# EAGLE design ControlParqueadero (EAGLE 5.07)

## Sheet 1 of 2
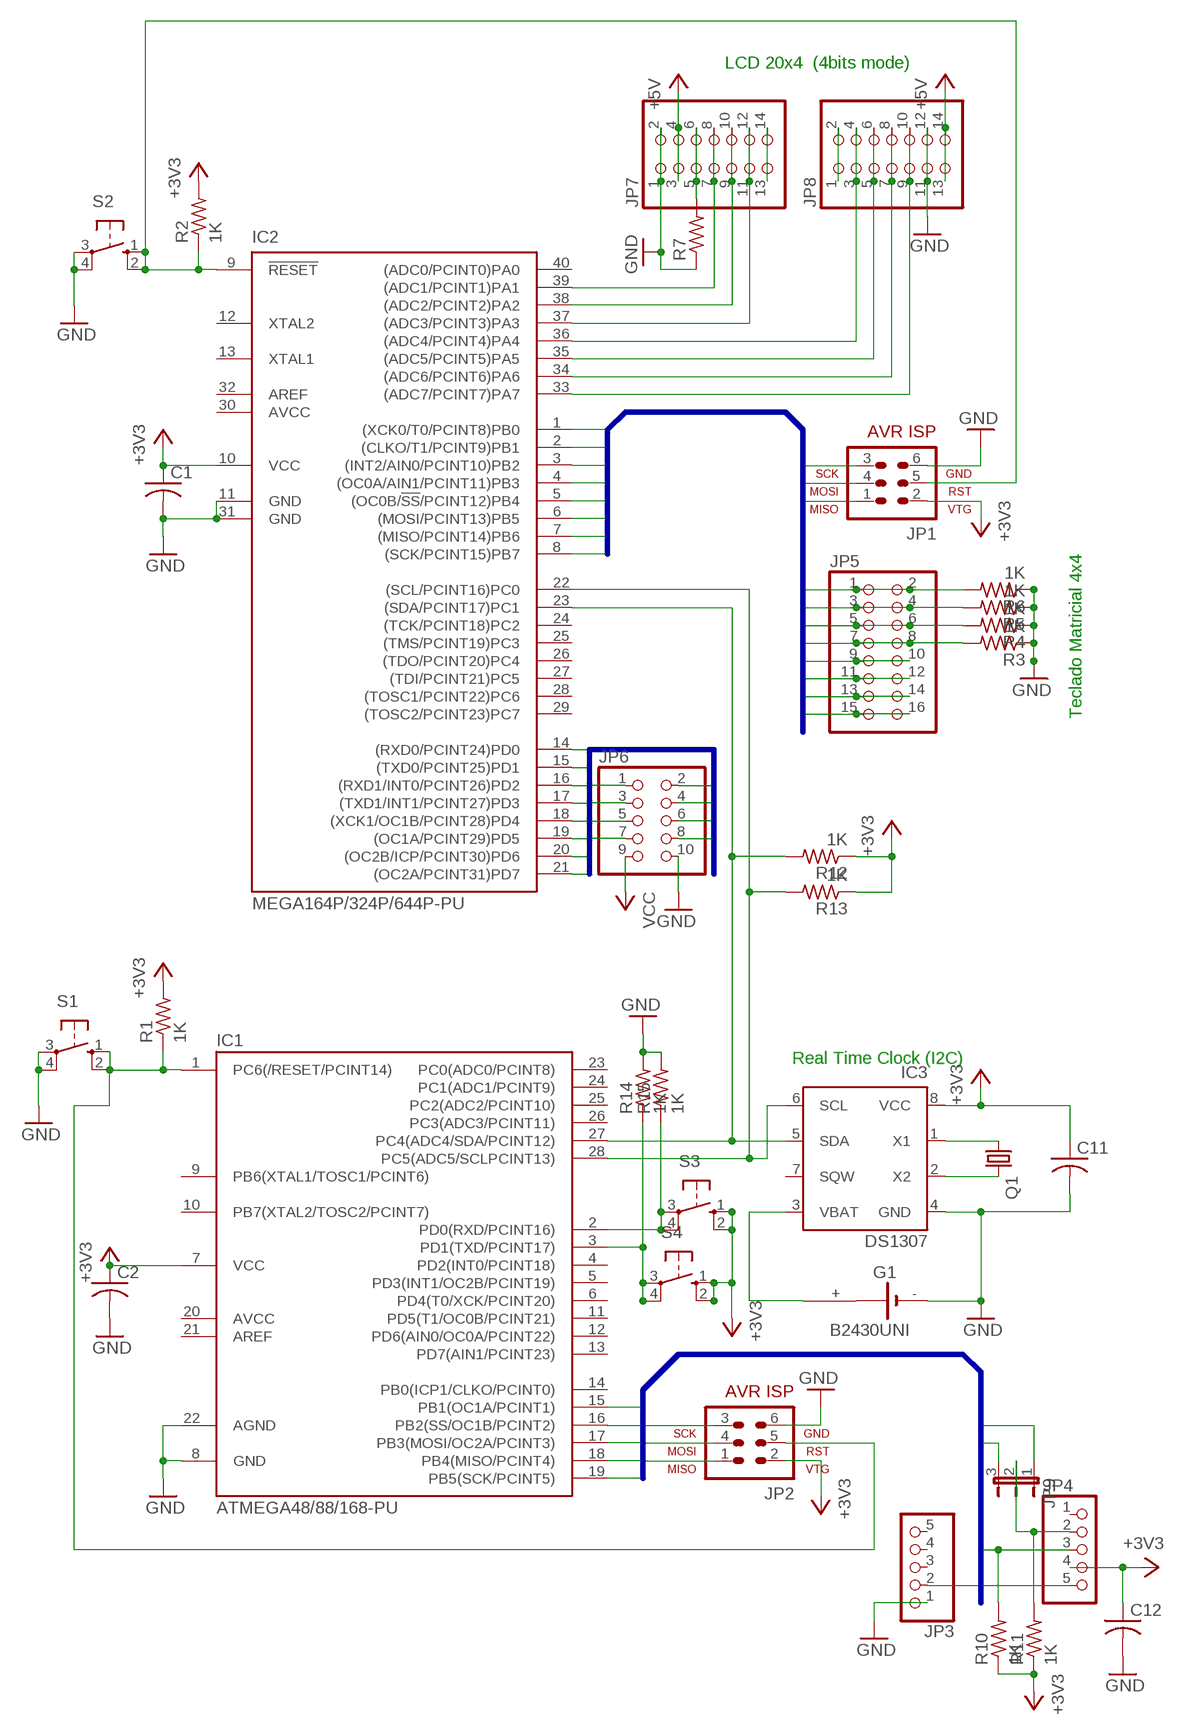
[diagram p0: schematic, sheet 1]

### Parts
C1  C-US025-025X050  [C025-025X050]
C2  C-US025-025X050  [C025-025X050]
C11  C-US025-025X050  [C025-025X050]
C12  C-US025-025X050  [C025-025X050]
G1  B2430UNI  [B2430UNI]
IC1  ATMEGA48/88/168-PU  [DIL28-3]
IC2  MEGA164P/324P/644P-PU  [DIL40]
IC3  DS1307  [DIL08]
JP1  AVR-ISP-6  [AVR-ISP-6]
JP2  AVR-ISP-6  [AVR-ISP-6]
JP3  PINHD-1X5  [1X05]
JP4  PINHD-1X5  [1X05]
JP5  PINHD-2X8  [2X08]
JP6  PINHD-2X5  [2X05]
JP7  PINHD-2X7  [2X07]
JP8  PINHD-2X7  [2X07]
JP9  JP2E  [JP2]
Q1  CRYSTALTC26V  [TC26V]
R1  1K  R-US_0204/7  [0204/7]
R2  1K  R-US_0204/7  [0204/7]
R3  1K  R-US_0204/7  [0204/7]
R4  1K  R-US_0204/7  [0204/7]
R5  1K  R-US_0204/7  [0204/7]
R6  1K  R-US_0204/7  [0204/7]
R7  R-US_0204/7  [0204/7]
R10  1K  R-US_0204/7  [0204/7]
R11  1K  R-US_0204/7  [0204/7]
R12  1K  R-US_0204/7  [0204/7]
R13  1K  R-US_0204/7  [0204/7]
R14  1K  R-US_0204/7  [0204/7]
R15  1K  R-US_0204/7  [0204/7]
S1  10-XX  [B3F-10XX]
S2  10-XX  [B3F-10XX]
S3  10-XX  [B3F-10XX]
S4  10-XX  [B3F-10XX]

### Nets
+3V3: C1.1 C2.1 C11.1 C12.1 IC1.7(VCC) IC2.10(VCC) IC3.8(VCC) JP1.2 JP2.2 JP4.4 R1.2 R2.2 R10.1 R11.1 R12.1 R13.1 S3.1(S) S3.2(S1) S4.1(S) S4.2(S1) ; also sheet 2
+5V: JP7.3 JP7.4 JP8.13 JP8.14 ; also sheet 2
GND: C1.2 C2.2 C11.2 C12.2 G1.- IC1.8(GND) IC1.22(AGND) IC2.11(GND) IC2.31(GND) IC3.4(GND) JP1.6 JP2.6 JP3.1 JP6.10 JP7.1 JP7.2 JP8.11 JP8.12 R3.1 R4.1 R5.1 R6.1 R7.1 R14.2 R15.2 S1.3(P) S1.4(P1) S2.3(P) S2.4(P1) ; also sheet 2
N$1: IC1.1(PC6(/RESET/PCINT14)) JP2.5 R1.1 S1.1(S) S1.2(S1)
N$2: IC1.2(PD0(RXD/PCINT16)) R15.1 S3.3(P) S3.4(P1)
N$3: IC2.9(!RESET) JP1.5 R2.1 S2.1(S) S2.2(S1)
N$4: IC1.3(PD1(TXD/PCINT17)) R14.1 S4.3(P) S4.4(P1)
N$5: JP4.2 JP9.2 R11.2
N$9: IC1.27(PC4(ADC4/SDA/PCINT12)) IC2.23((SDA/PCINT17)PC1) IC3.5(SDA) R12.2
N$11: IC1.28(PC5(ADC5/SCLPCINT13)) IC2.22((SCL/PCINT16)PC0) IC3.6(SCL) R13.2
N$19: IC3.2(X2) Q1.2
N$22: G1.+ IC3.3(VBAT)
N$27: IC2.33((ADC7/PCINT7)PA7) JP8.9 JP8.10
N$28: IC2.34((ADC6/PCINT6)PA6) JP8.7 JP8.8
N$29: IC2.35((ADC5/PCINT5)PA5) JP8.5 JP8.6
N$30: IC2.36((ADC4/PCINT4)PA4) JP8.3 JP8.4
N$32: IC3.1(X1) Q1.1
N$37: JP7.5 JP7.6 R7.2
N$38: IC2.39((ADC1/PCINT1)PA1) JP7.7 JP7.8
N$39: IC2.38((ADC2/PCINT2)PA2) JP7.9 JP7.10
N$40: IC2.37((ADC3/PCINT3)PA3) JP7.11 JP7.12
N$41: JP7.13 JP7.14
N$42: JP8.1 JP8.2
PORTB1: IC1.15(PB1(OC1A/PCINT1)) JP9.1
PORTB2: IC1.16(PB2(SS/OC1B/PCINT2)) JP9.3
PORTB3: IC1.17(PB3(MOSI/OC2A/PCINT3)) JP2.4 JP4.3 R10.2
PORTB4: IC1.18(PB4(MISO/PCINT4)) JP2.1 JP3.2
PORTB5: IC1.19(PB5(SCK/PCINT5)) JP2.3 JP4.5
PORTB_A0: IC2.1((XCK0/T0/PCINT8)PB0) JP5.1 JP5.2 R6.2
PORTB_A1: IC2.2((CLKO/T1/PCINT9)PB1) JP5.3 JP5.4 R5.2
PORTB_A2: IC2.3((INT2/AIN0/PCINT10)PB2) JP5.5 JP5.6 R4.2
PORTB_A3: IC2.4((OC0A/AIN1/PCINT11)PB3) JP5.7 JP5.8 R3.2
PORTB_A4: IC2.5((OC0B/!SS!/PCINT12)PB4) JP5.9 JP5.10
PORTB_A5: IC2.6((MOSI/PCINT13)PB5) JP1.4 JP5.11 JP5.12
PORTB_A6: IC2.7((MISO/PCINT14)PB6) JP1.1 JP5.13 JP5.14
PORTB_A7: IC2.8((SCK/PCINT15)PB7) JP1.3 JP5.15 JP5.16
PORTC0: IC2.14((RXD0/PCINT24)PD0) JP6.1
PORTC1: IC2.15((TXD0/PCINT25)PD1) JP6.2
PORTC2: IC2.16((RXD1/INT0/PCINT26)PD2) JP6.3
PORTC3: IC2.17((TXD1/INT1/PCINT27)PD3) JP6.4
PORTC4: IC2.18((XCK1/OC1B/PCINT28)PD4) JP6.5
PORTC5: IC2.19((OC1A/PCINT29)PD5) JP6.6
PORTC6: IC2.20((OC2B/ICP/PCINT30)PD6) JP6.7
PORTC7: IC2.21((OC2A/PCINT31)PD7) JP6.8
VCC: JP6.9 ; also sheet 2
Unconnected: G1.+@1(+) G1.+@2(+) G1.+@3(+) G1.+@4(+) G1.-@1(-) IC1.4(PD2(INT0/PCINT18)) IC1.5(PD3(INT1/OC2B/PCINT19)) IC1.6(PD4(T0/XCK/PCINT20)) IC1.9(PB6(XTAL1/TOSC1/PCINT6)) IC1.10(PB7(XTAL2/TOSC2/PCINT7)) IC1.11(PD5(T1/OC0B/PCINT21)) IC1.12(PD6(AIN0/OC0A/PCINT22)) IC1.13(PD7(AIN1/PCINT23)) IC1.14(PB0(ICP1/CLKO/PCINT0)) IC1.20(AVCC) IC1.21(AREF) IC1.23(PC0(ADC0/PCINT8)) IC1.24(PC1(ADC1/PCINT9)) IC1.25(PC2(ADC2/PCINT10)) IC1.26(PC3(ADC3/PCINT11)) IC2.12(XTAL2) IC2.13(XTAL1) IC2.24((TCK/PCINT18)PC2) IC2.25((TMS/PCINT19)PC3) IC2.26((TDO/PCINT20)PC4) IC2.27((TDI/PCINT21)PC5) IC2.28((TOSC1/PCINT22)PC6) IC2.29((TOSC2/PCINT23)PC7) IC2.40((ADC0/PCINT0)PA0) IC3.7(SQW) JP3.3 JP3.4 JP3.5 JP4.1

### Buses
PORTB[0..5]
PORTC[0..7]
PORTB_A[0..7]

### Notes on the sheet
- LCD 20x4  (4bits mode)
- Teclado Matricial 4x4
- Real Time Clock (I2C)

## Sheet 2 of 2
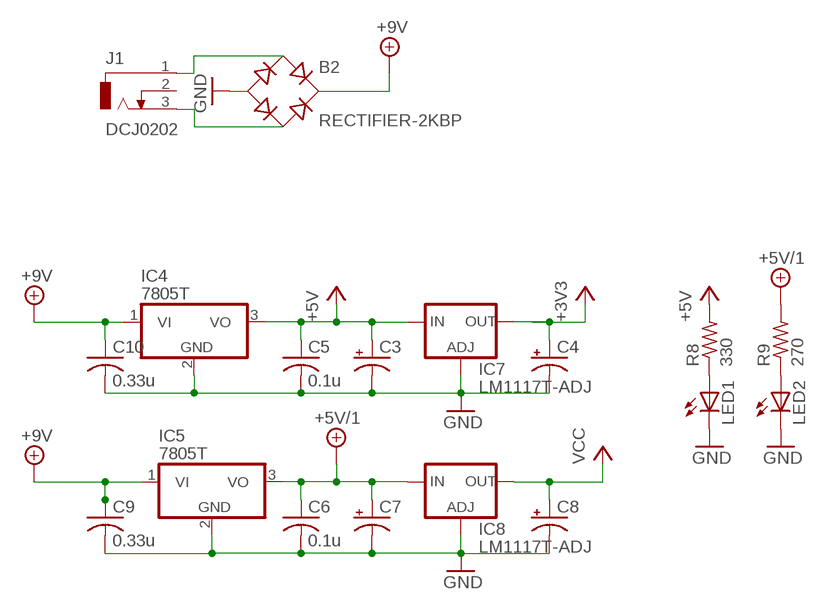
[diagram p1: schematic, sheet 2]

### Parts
B2  RECTIFIER-2KBP  [2KBP]
C3  CPOL-USE5-8.5  [E5-8,5]
C4  CPOL-USE5-8.5  [E5-8,5]
C5  0.1u  C-US025-025X050  [C025-025X050]
C6  0.1u  C-US025-025X050  [C025-025X050]
C7  CPOL-USE5-8.5  [E5-8,5]
C8  CPOL-USE5-8.5  [E5-8,5]
C9  0.33u  C-US050-035X075  [C050-035X075]
C10  0.33u  C-US050-035X075  [C050-035X075]
IC4  7805T  [TO220H]
IC5  7805T  [TO220H]
IC7  LM1117T-ADJ  [TO220]
IC8  LM1117T-ADJ  [TO220]
J1  DCJ0202  [DCJ0202]
LED1  LED5MM  [LED5MM]
LED2  LED5MM  [LED5MM]
R8  330  R-US_0204/7  [0204/7]
R9  270  R-US_0204/7  [0204/7]

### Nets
+3V3: C4.+ IC7.2(OUT) ; also sheet 1
+5V: C3.+ C5.1 IC4.3(VO) IC7.3(IN) R8.2 ; also sheet 1
+5V/1: C6.1 C7.+ IC5.3(VO) IC8.3(IN) R9.2
+9V: B2.+ C9.1 C10.1 IC4.1(VI) IC5.1(VI)
GND: B2.- C3.- C4.- C5.2 C6.2 C7.- C8.- C9.2 C10.2 IC4.2(GND) IC5.2(GND) IC7.1(ADJ) IC8.1(ADJ) LED1.K(C) LED2.K(C) ; also sheet 1
N$21: LED1.A R8.1
N$23: B2.AC1 J1.1
N$24: B2.AC2 J1.3
N$25: LED2.A R9.1
VCC: C8.+ IC8.2(OUT) ; also sheet 1
Unconnected: J1.2

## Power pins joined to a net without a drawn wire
AREF: IC2.32(AREF)
AVCC: IC2.30(AVCC)

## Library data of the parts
B2 = rectifier:RECTIFIER-: Rectifier
C1 C2 C5 C6 C9-C12 = rcl:C-US: CAPACITOR, American symbol
C3 C4 C7 C8 = rcl:CPOL-US: POLARIZED CAPACITOR, American symbol
G1 = battery:B2430UNI: LI BATTERY
IC1 = atmega8:ATMEGA48/88/168-PU
IC2 = avr-6:MEGA164P/324P/644P-PU
IC3 = ds1307_pcf8583:DS1307: I2C-Bus CLOCK/CALENDAR
IC4 IC5 = linear:78*: Positive VOLTAGE REGULATOR Source: http://cache.national.com/ds/LM/LM78L05.pdf http://www.fairchildsemi.com/ds/LM/LM7805.pdf
IC7 IC8 = lm1117:LM1117T-ADJ
J1 = con-jack:DCJ0202: DC POWER JACK Source: DCJ0202.pdf
JP1 JP2 = avr-6:AVR-ISP-6: AVR ISP-6 Serial Programming Header
JP3 JP4 = pinhead:PINHD-1X5: PIN HEADER
JP5 = pinhead:PINHD-2X8: PIN HEADER
JP6 = pinhead:PINHD-2X5: PIN HEADER
JP7 JP8 = pinhead:PINHD-2X7: PIN HEADER
JP9 = jumper:JP2E: JUMPER
LED1 LED2 = led:LED: LED
Q1 = crystal:CRYSTAL: CRYSTAL
R1-R15 = rcl:R-US_: RESISTOR, American symbol
S1-S4 = switch-omron:10-XX: OMRON SWITCH

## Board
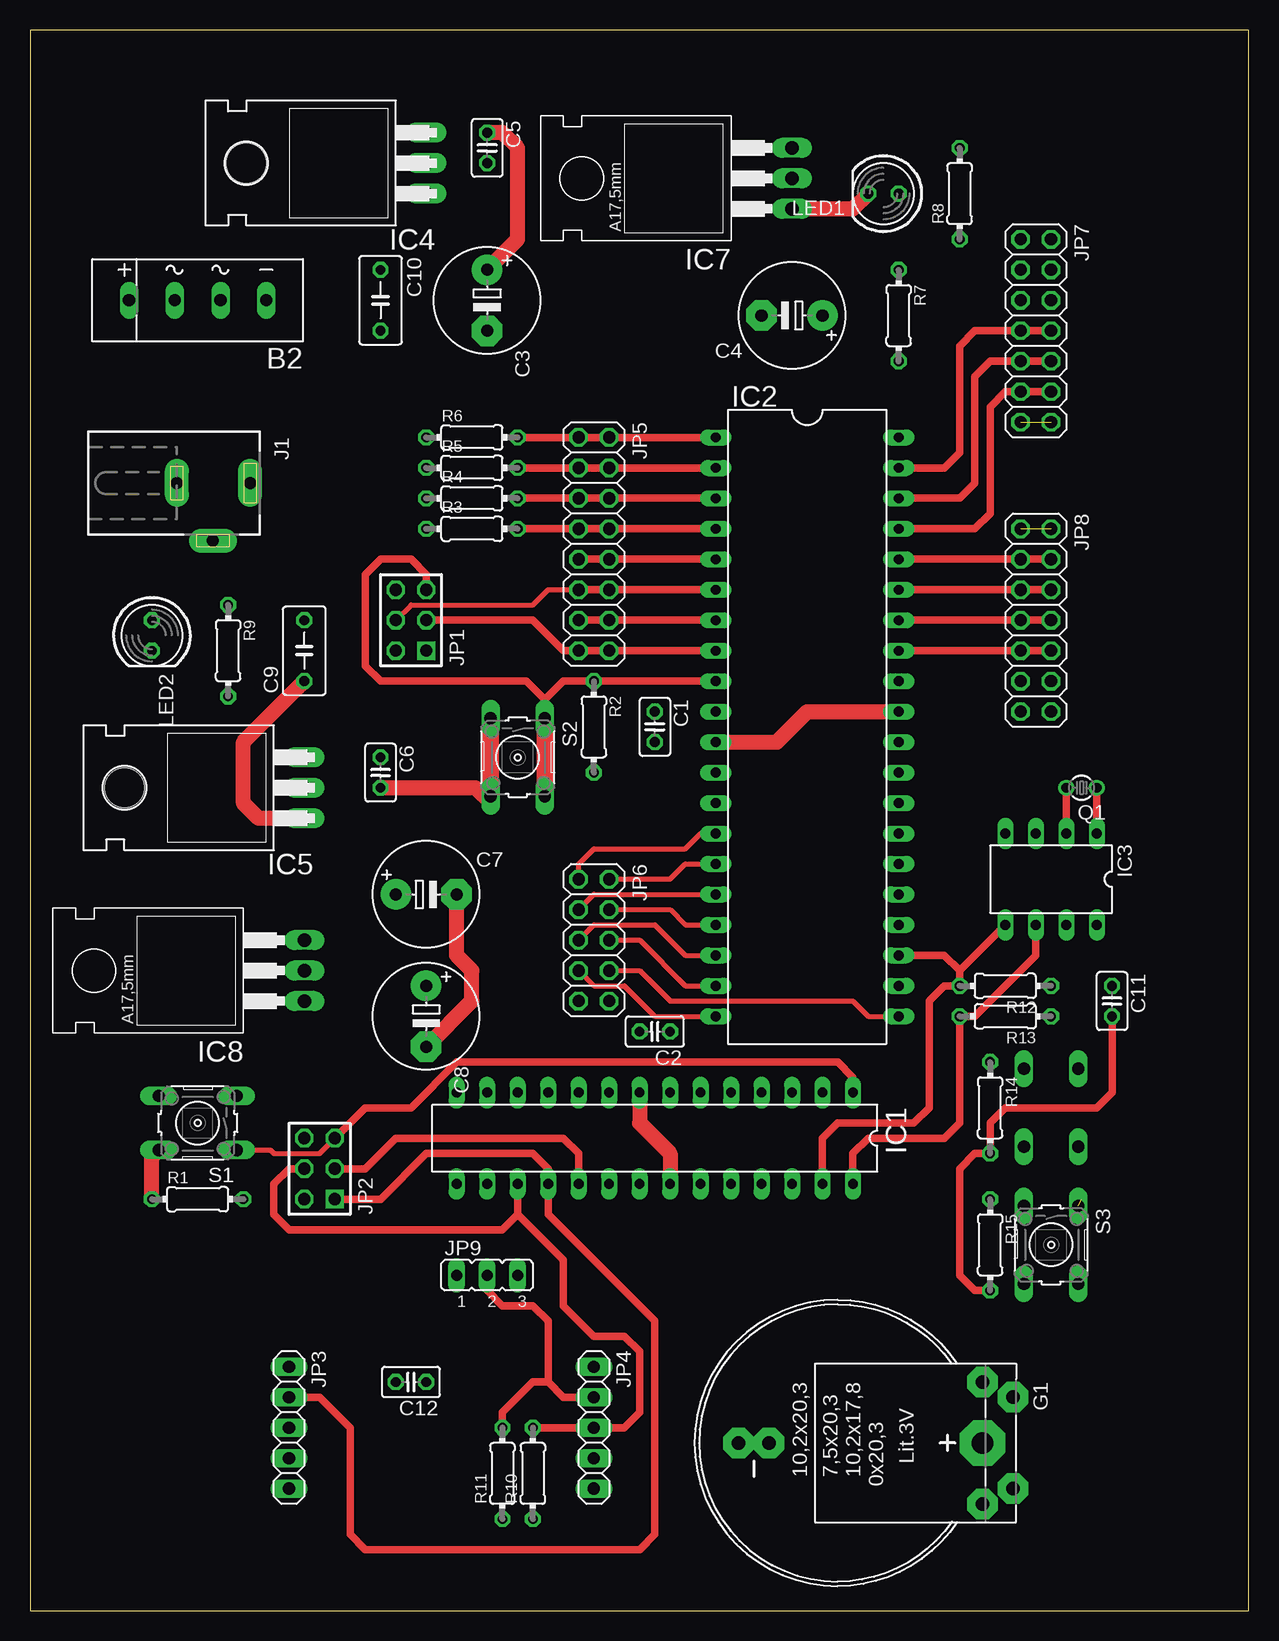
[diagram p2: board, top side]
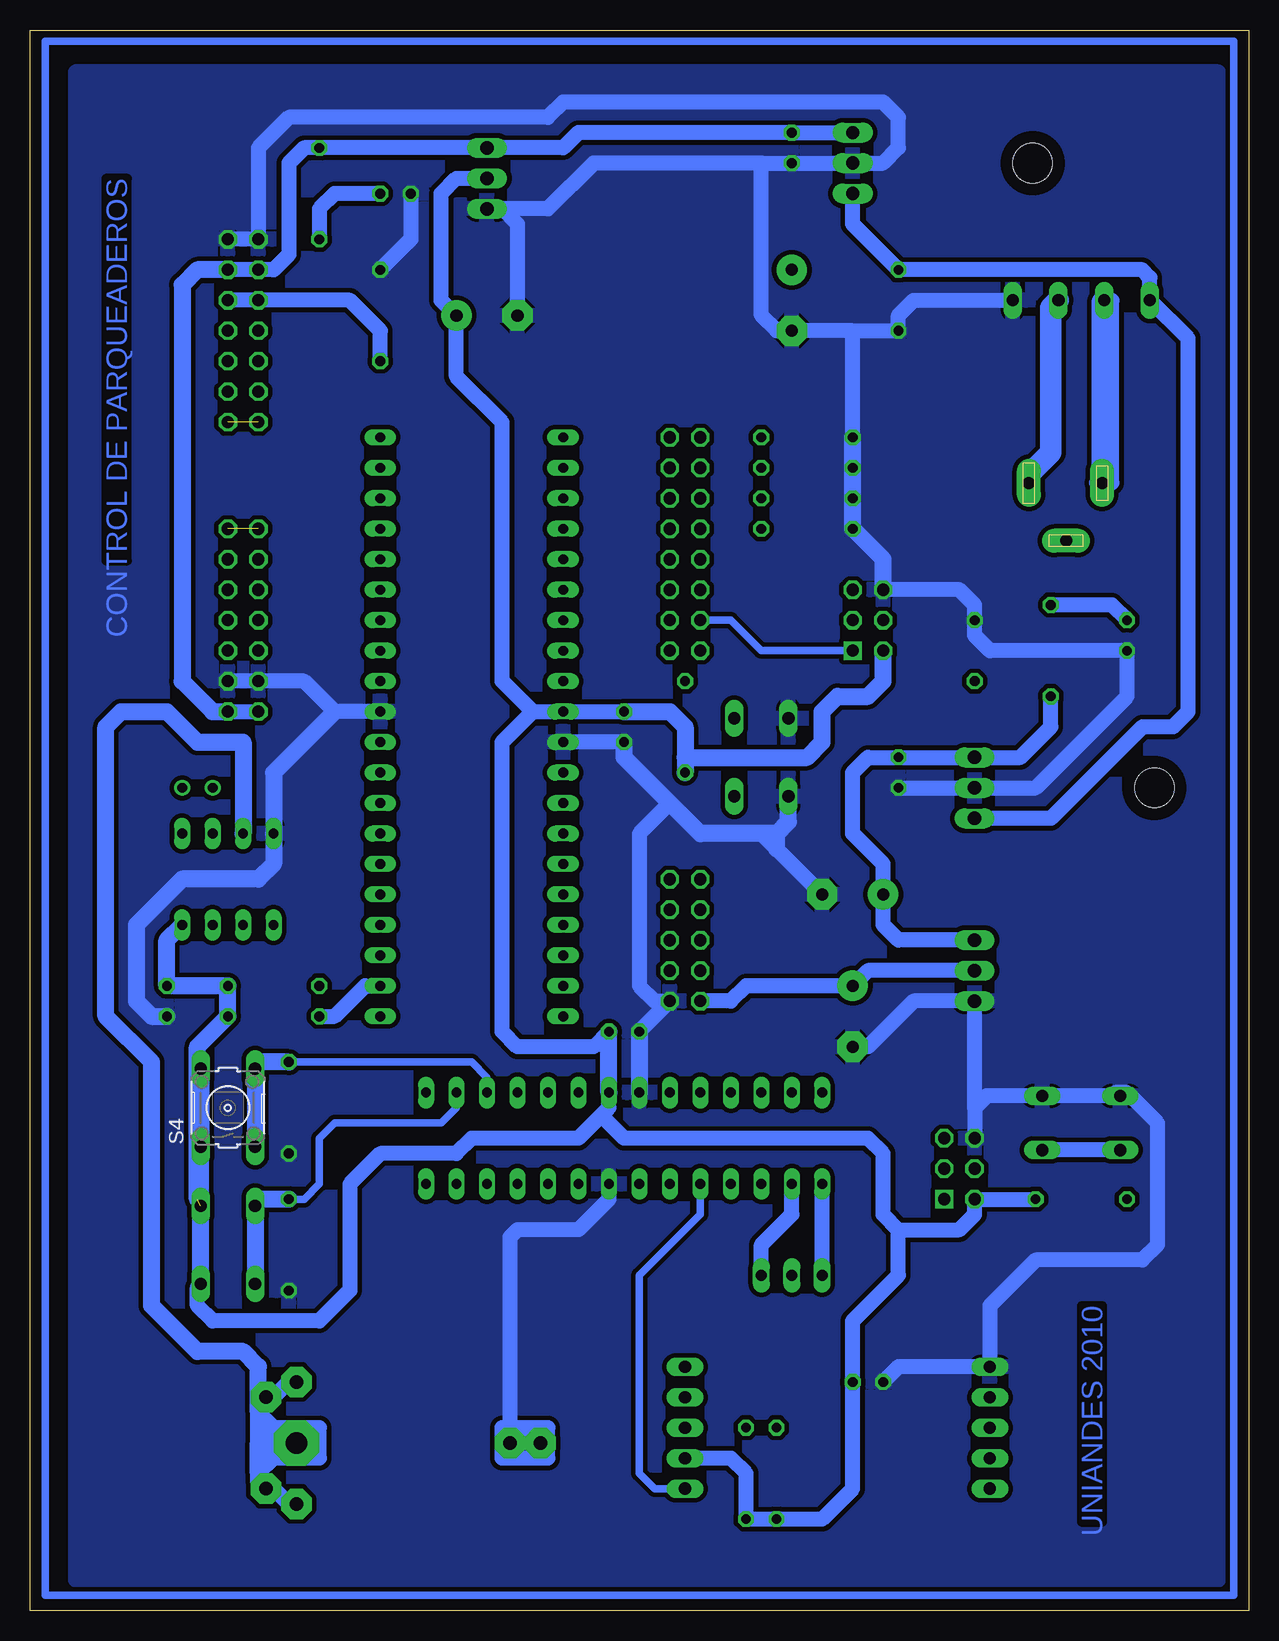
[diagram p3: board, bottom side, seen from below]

Size 101.58 x 131.75 mm. Coordinates in mm from the lower left corner, seen from the top.
Outline: 0,0 101.58,0 101.58,131.75 0,131.75 0,0
Copper layers (1*16): Top 0.035mm / dielectric 1.5mm / Bottom 0.035mm
Design rules "default *": minimum track width 10mil, minimum drill 24mil, track to track 15mil, track to pad 15mil, pad to pad 15mil, via to via 15mil, smd to smd 8mil, copper to edge 40mil, drill to drill 8mil, minimum pad ring 10mil, minimum via ring 8mil, stop-mask expansion 4mil, vias tented up to drill 0mil, thermal gap 10mil

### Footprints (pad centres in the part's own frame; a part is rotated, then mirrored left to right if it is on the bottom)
2KBP = drill 1.016 long: + 5.715,0; - -5.715,0; AC1 -1.905,0; AC2 1.905,0
C025-025X050 = drill 0.813 octagon: 1 -1.27,0; 2 1.27,0
E5-8,5 = drill 1.016 pad 2.54 round: + -2.54,0 | drill 1.016 pad 2.54 octagon: - 2.54,0
C050-035X075 = drill 0.813 octagon: 1 -2.54,0; 2 2.54,0
B2430UNI = drill 1.118 pad 2.54 octagon: + 3.81,14.605; +@1 -3.81,14.605; +@2 -5.08,12.065; +@3 5.08,12.065; - 0,-5.715; -@1 0,-8.255 | drill 1.803 pad 3.81 octagon: +@4 0,12.065
DIL28-3 = drill 0.813 long: 1 -16.51,-3.81; 2 -13.97,-3.81; 3 -11.43,-3.81; 4 -8.89,-3.81; 5 -6.35,-3.81; 6 -3.81,-3.81; 7 -1.27,-3.81; 8 1.27,-3.81; 9 3.81,-3.81; 10 6.35,-3.81; 11 8.89,-3.81; 12 11.43,-3.81; 13 13.97,-3.81; 14 16.51,-3.81; 15 16.51,3.81; 16 13.97,3.81; 17 11.43,3.81; 18 8.89,3.81; 19 6.35,3.81; 20 3.81,3.81; 21 1.27,3.81; 22 -1.27,3.81; 23 -3.81,3.81; 24 -6.35,3.81; 25 -8.89,3.81; 26 -11.43,3.81; 27 -13.97,3.81; 28 -16.51,3.81
DIL40 = drill 0.813 long: 1 -24.13,-7.62; 2 -21.59,-7.62; 3 -19.05,-7.62; 4 -16.51,-7.62; 5 -13.97,-7.62; 6 -11.43,-7.62; 7 -8.89,-7.62; 8 -6.35,-7.62; 9 -3.81,-7.62; 10 -1.27,-7.62; 11 1.27,-7.62; 12 3.81,-7.62; 13 6.35,-7.62; 14 8.89,-7.62; 15 11.43,-7.62; 16 13.97,-7.62; 17 16.51,-7.62; 18 19.05,-7.62; 19 21.59,-7.62; 20 24.13,-7.62; 21 24.13,7.62; 22 21.59,7.62; 23 19.05,7.62; 24 16.51,7.62; 25 13.97,7.62; 26 11.43,7.62; 27 8.89,7.62; 28 6.35,7.62; 29 3.81,7.62; 30 1.27,7.62; 31 -1.27,7.62; 32 -3.81,7.62; 33 -6.35,7.62; 34 -8.89,7.62; 35 -11.43,7.62; 36 -13.97,7.62; 37 -16.51,7.62; 38 -19.05,7.62; 39 -21.59,7.62; 40 -24.13,7.62
DIL08 = drill 0.813 long: 1 -3.81,-3.81; 2 -1.27,-3.81; 3 1.27,-3.81; 4 3.81,-3.81; 5 3.81,3.81; 6 1.27,3.81; 7 -1.27,3.81; 8 -3.81,3.81
TO220H = drill 1.118 long: 1 -2.54,-10.16; 2 0,-10.16; 3 2.54,-10.16 | hole 3.302: 0,4.826
TO220 = drill 1.118 long: 1 -2.54,-6.35; 2 0,-6.35; 3 2.54,-6.35
DCJ0202 = drill 1 pad 2 long: 1 0,3.1; 2 4.8,0; 3 0,-3
AVR-ISP-6 = drill 1.016 square: 1 -2.54,-1.27 | drill 1.016 octagon: 2 -2.54,1.27; 3 0,-1.27; 4 0,1.27; 5 2.54,-1.27; 6 2.54,1.27
1X05 = drill 1.016 long: 1 -5.08,0; 2 -2.54,0; 3 0,0; 4 2.54,0; 5 5.08,0
2X08 = drill 1.016 octagon: 1 -8.89,-1.27; 2 -8.89,1.27; 3 -6.35,-1.27; 4 -6.35,1.27; 5 -3.81,-1.27; 6 -3.81,1.27; 7 -1.27,-1.27; 8 -1.27,1.27; 9 1.27,-1.27; 10 1.27,1.27; 11 3.81,-1.27; 12 3.81,1.27; 13 6.35,-1.27; 14 6.35,1.27; 15 8.89,-1.27; 16 8.89,1.27
2X05 = drill 1.016 octagon: 1 -5.08,-1.27; 2 -5.08,1.27; 3 -2.54,-1.27; 4 -2.54,1.27; 5 0,-1.27; 6 0,1.27; 7 2.54,-1.27; 8 2.54,1.27; 9 5.08,-1.27; 10 5.08,1.27
2X07 = drill 1.016 octagon: 1 -7.62,-1.27; 2 -7.62,1.27; 3 -5.08,-1.27; 4 -5.08,1.27; 5 -2.54,-1.27; 6 -2.54,1.27; 7 0,-1.27; 8 0,1.27; 9 2.54,-1.27; 10 2.54,1.27; 11 5.08,-1.27; 12 5.08,1.27; 13 7.62,-1.27; 14 7.62,1.27
JP2 = drill 0.914 long: 1 -2.54,0; 2 0,0; 3 2.54,0
LED5MM = drill 0.813 octagon: A -1.27,0; K 1.27,0
TC26V = drill 0.813 round: 1 -1.27,0; 2 1.27,0
0204/7 = drill 0.813 octagon: 1 -3.81,0; 2 3.81,0
B3F-10XX = drill 1.016 long: 1 -3.251,2.261; 2 3.251,2.261; 3 -3.251,-2.261; 4 3.251,-2.261

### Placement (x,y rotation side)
B2  13.97,109.22 180 top
C1  52.07,73.66 270 top
C2  52.07,48.26 180 top
C3  38.1,109.22 270 top
C4  63.5,107.95 180 top
C5  38.1,121.92 270 top
C6  29.21,69.85 270 top
C7  33.02,59.69 0 top
C8  33.02,49.53 270 top
C9  22.86,80.01 90 top
C10  29.21,109.22 270 top
C11  90.17,50.8 270 top
C12  31.75,19.05 180 top
G1  67.31,13.97 270 top
IC1  52.07,39.37 180 top
IC2  64.77,73.66 270 top
IC3  85.09,60.96 180 top
IC4  22.86,120.65 90 top
IC5  12.7,68.58 90 top
IC7  57.15,119.38 90 top
IC8  16.51,53.34 90 top
J1  15.24,93.98 270 top
JP1  31.75,82.55 90 top
JP2  24.13,36.83 90 top
JP3  21.59,15.24 270 top
JP4  46.99,15.24 270 top
JP5  46.99,88.9 270 top
JP6  46.99,55.88 270 top
JP7  83.82,106.68 270 top
JP8  83.82,82.55 270 top
JP9  38.1,27.94 0 top
LED1  71.12,118.11 180 top
LED2  10.16,81.28 270 top
Q1  87.63,68.58 180 top
R1  13.97,34.29 0 top
R2  46.99,73.66 270 top
R3  36.83,90.17 0 top
R4  36.83,92.71 0 top
R5  36.83,95.25 0 top
R6  36.83,97.79 0 top
R7  72.39,107.95 270 top
R8  77.47,118.11 90 top
R9  16.51,80.01 270 top
R10  41.91,11.43 90 top
R11  39.37,11.43 90 top
R12  81.28,52.07 180 top
R13  81.28,49.53 180 top
R14  80.01,41.91 270 top
R15  80.01,30.48 270 top
S1  13.97,40.64 180 top
S2  40.64,71.12 270 top
S3  85.09,30.48 270 top
S4  85.09,41.91 90 bottom

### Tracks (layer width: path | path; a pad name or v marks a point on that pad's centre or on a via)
+3V3  (1 unrouted)
  Bottom 1.27: C1.1 IC2.10 59.69,74.93 | IC7.2 66.04,119.38 67.31,118.11 67.31,109.22 C4.+ 66.04,102.87 62.23,99.06 62.23,77.47 59.69,74.93 | IC1.7 53.34,41.91 53.97,41.27 | 53.97,41.27 55.88,39.37 64.77,39.37 66.04,38.1 72.39,38.1 74.93,35.56 74.93,26.67 77.47,24.13 86.36,24.13 87.63,25.4 87.63,26.95 S3.2 | 29.21,31.75 24.13,31.75 22.86,33.02 JP2.2 R1.2 | 29.21,31.75 30.48,33.02 30.48,38.1 31.75,39.37 52.07,39.37 53.97,41.27 | C2.1 54.61,46.99 60.96,46.99 62.23,48.26 62.23,72.39 59.69,74.93 | 29.21,31.75 29.21,27.94 33.02,24.13 C12.1 33.02,10.16 35.56,7.62 R11.1 R10.1 41.91,11.43 43.18,12.7 JP4.4
  Bottom 1.422: 46.99,71.12 46.99,73.66 48.26,74.93 C1.1 | 46.99,71.12 R2.2 | 46.99,71.12 36.83,71.12 35.56,72.39 35.56,74.93 34.29,76.2 31.75,76.2 30.48,77.47 JP1.2 | IC1.7 C2.1 | IC3.8 90.17,55.88 C11.1 R12.1 R13.1 87.63,46.99 87.63,34.29 87.35,34.57 S4.2 S4.1 | S3.2 S3.1
+5V
  Top 1.27: C3.+ 40.64,114.3 40.64,121.92 39.37,123.19 C5.1
  Bottom 1.27: JP7.4 JP7.3 81.28,111.76 80.01,113.03 80.01,120.65 78.74,121.92 R8.2 IC7.3 57.15,121.92 55.88,123.19 C5.1 IC4.3 | JP8.14 JP8.13
  Bottom 1.422: JP8.14 86.36,74.93 88.9,77.47 88.9,110.49 87.63,111.76 JP7.4
+5V/1
  Bottom 1.27: R9.2 16.51,73.66 19.05,71.12 IC5.3 C6.1 31.75,71.12 33.02,69.85 33.02,64.77 30.48,62.23 C7.+ 30.48,57.15 29.21,55.88 IC8.3
+9V
  Top 1.27: C9.1 17.78,72.39 17.78,67.31 19.05,66.04 IC5.1
  Bottom 1.27: IC4.1 33.02,115.57 C10.1 8.89,111.76 8.25,111.12 B2.+ 5.08,106.04 5.08,74.93 6.35,73.66 8.89,73.66 16.51,66.04 IC5.1
GND
  Top 0.61: R15.2 78.74,26.67 77.47,27.94 77.47,36.83 78.74,38.1 R14.2 80.01,40.64 81.28,41.91 88.9,41.91 90.17,43.18 C11.2
  Top 1.27: IC7.1 68.58,116.84 LED1.K | C6.2 37.11,68.58 38.38,67.31 38.38,69.85 | IC1.8 50.8,40.64 53.34,38.1 IC1.22 | C7.- 35.56,54.61 36.83,53.34 36.83,50.8 C8.- | IC2.11 62.23,72.39 64.77,74.93 IC2.31
  Top 1.422: S2.4 38.38,69.85 S2.3
  Bottom 1.27: JP7.2 JP7.1 82.55,121.92 80.01,124.46 58.42,124.46 57.15,125.73 30.48,125.73 29.21,124.46 29.21,121.92 30.48,120.65 IC4.2 C5.2 40.64,120.65 | JP8.12 JP8.11 78.74,77.47 76.2,74.93 IC2.31 | C1.2 IC2.11 | B2.- 27.94,109.22 29.21,107.95 C10.2 33.02,106.68 | 62.23,116.84 58.42,116.84 54.61,120.65 40.64,120.65 | 33.02,106.68 C3.- 39.37,106.68 40.64,107.95 40.64,120.65 | R7.1 69.85,114.3 LED1.K | 62.23,116.84 IC7.1 | 62.23,116.84 60.96,115.57 C4.- | C6.2 IC5.2 17.78,68.58 10.16,76.2 LED2.K 21.59,80.01 22.86,81.28 C9.2 22.86,83.82 24.13,85.09 JP1.6 | C8.- 31.75,46.99 27.94,50.8 IC8.1 22.86,41.91 | R6.1 33.02,106.68 | C2.2 JP6.10 49.53,50.8 50.8,52.07 50.8,64.77 48.26,67.31 | 22.86,41.91 JP2.6 | C7.- 39.37,63.5 40.64,64.77 | G1.- 61.59,31.11 60.96,31.75 55.88,31.75 53.34,34.29 IC1.22 | 22.86,41.91 21.87,42.9 S1.3 11.43,42.9 | 11.43,42.9 S1.4 | C12.2 29.21,20.32 JP3.1 21.59,25.4 17.78,29.21 8.89,29.21 7.62,30.48 7.62,40.64 10.16,43.18 11.15,43.18 11.43,42.9
  Bottom 1.422: S2.4 38.38,65.76 39.37,64.77 | C1.2 52.07,71.12 48.26,67.31 45.72,64.77 40.64,64.77 39.37,64.77 | R6.1 R5.1 R4.1 R3.1 30.48,87.63 JP1.6 | C2.2 IC1.8 | 76.2,74.93 81.28,69.85 IC3.4 81.28,62.23 82.55,60.96 88.9,60.96 92.71,57.15 92.71,50.8 91.44,49.53 C11.2 | 39.37,63.5 39.37,64.77
  pour Bottom: 2.54,128.27 97.79,128.27 97.79,13.97 97.79,2.54 7.62,2.54 2.54,2.54
N$1
  Top 0.406: S1.1 20.04,38.38 20.32,38.1 24.13,38.1 JP2.5
  Top 0.61: IC1.1 68.58,44.45 67.31,45.72 35.56,45.72 31.75,41.91 27.94,41.91 JP2.5
  Top 1.27: R1.1 10.16,37.82 S1.2
  Bottom 1.27: S1.2 S1.1
N$2
  Bottom 0.61: IC1.2 66.04,41.91 67.31,40.64 76.2,40.64 77.47,39.37 77.47,35.56 78.74,34.29 R15.1
  Bottom 1.422: S3.4 S3.3 82.83,34.01 82.55,34.29 R15.1
N$3
  Top 0.61: 42.9,75.92 S2.1 | 42.9,75.92 44.45,77.47 R2.1 IC2.9 | JP1.5 33.02,86.36 31.75,87.63 29.21,87.63 27.94,86.36 27.94,78.74 29.21,77.47 41.35,77.47 42.9,75.92
  Top 1.422: S2.1 S2.2
N$4
  Bottom 0.61: IC1.3 63.5,44.45 64.77,45.72 R14.1
  Bottom 1.422: R14.1 82.55,45.72 82.83,45.44 S4.4 S4.3
N$5
  Top 0.61: JP4.2 44.45,17.78 43.18,19.05 | 43.18,19.05 43.18,24.13 41.91,25.4 39.37,25.4 38.1,26.67 JP9.2 | R11.2 39.37,16.51 41.91,19.05 43.18,19.05
N$6
  Bottom 1.27: 62.23,13.97 60.96,13.97 58.42,13.97
N$7
  Bottom 1.27: 60.96,15.24 58.42,15.24 58.42,12.7 62.23,12.7 62.23,15.24
N$8
  Bottom 0.61: 1.27,130.81 100.33,130.81 100.33,1.27 1.27,1.27 1.27,130.81
N$9
  Top 0.61: 77.47,53.34 R12.2 76.2,52.07 74.93,50.8 74.93,41.91 73.66,40.64 67.31,40.64 66.04,39.37 IC1.27 | 77.47,53.34 76.2,54.61 IC2.23 | 77.47,53.34 IC3.5
N$10
  Bottom 1.27: 11.43,109.22 11.43,93.98 12.7,93.98
N$11
  Top 0.61: IC3.6 83.82,54.61 78.74,49.53 R13.2 77.47,40.64 76.2,39.37 69.85,39.37 68.58,38.1 IC1.28
  Bottom 1.27: R13.2 76.2,49.53 73.66,52.07 IC2.22
N$19
  Top 0.61: IC3.2 Q1.2
N$21
  Bottom 1.27: LED1.A 76.2,118.11 77.47,116.84 R8.1
N$22
  Bottom 1.27: 82.55,13.97 81.28,13.97 | 81.28,13.97 78.74,13.97 | 81.28,13.97 82.55,15.24 82.55,12.7 81.28,13.97 | 78.74,8.89 80.01,8.89 82.55,11.43 | 82.55,11.43 82.55,16.51 | 82.55,16.51 81.28,17.78 | 81.28,15.24 77.47,15.24 77.47,12.7 81.28,12.7 | 81.28,15.24 82.55,16.51 | 81.28,12.7 81.28,15.24 | 81.28,12.7 82.55,11.43 | 82.55,17.78 81.28,17.78 | 81.28,17.78 80.01,19.05 78.74,19.05
  Bottom 1.422: IC3.3 83.82,72.39 87.63,72.39 90.17,74.93 93.98,74.93 95.25,73.66 95.25,49.53 91.44,45.72 91.44,25.4 87.63,21.59 83.82,21.59 82.55,20.32 82.55,17.78 82.55,16.51 82.55,15.24 82.55,13.97 82.55,12.7 82.55,11.43 82.55,10.79 G1.+
N$23
  Bottom 1.778: J1.1 18.34,94.69 16.51,96.52 16.51,108.59 B2.AC1
N$24
  Bottom 1.778: J1.3 12.24,109.04 B2.AC2
N$25
  Bottom 1.27: LED2.A 11.43,83.82 R9.1
N$27
  Top 0.61: IC2.33 JP8.9 JP8.10
N$28
  Top 0.61: IC2.34 JP8.7 JP8.8
N$29
  Top 0.61: IC2.35 JP8.5 JP8.6
N$30
  Top 0.61: IC2.36 JP8.3 JP8.4
N$32
  Top 0.61: IC3.1 Q1.1
N$37
  Bottom 1.27: R7.2 72.39,106.68 74.93,109.22 JP7.5 JP7.6
N$38
  Top 0.61: JP7.8 JP7.7 78.74,106.68 77.47,105.41 77.47,96.52 76.2,95.25 IC2.39
N$39
  Top 0.61: JP7.10 JP7.9 80.01,104.14 78.74,102.87 78.74,93.98 77.47,92.71 IC2.38
N$40
  Top 0.61: JP7.12 JP7.11 81.28,101.6 80.01,100.33 80.01,91.44 78.74,90.17 IC2.37
N$41  (1 unrouted)
N$42  (1 unrouted)
PORTB1
  Bottom 1.27: JP9.1 IC1.15
PORTB2
  Bottom 1.27: JP9.3 40.64,30.48 38.1,33.02 IC1.16
PORTB3
  Top 0.61: JP2.4 21.59,36.83 20.32,35.56 20.32,33.02 21.59,31.75 39.37,31.75 40.64,33.02 | 40.64,33.02 IC1.17 | 40.64,33.02 44.45,29.21 44.45,25.4 46.99,22.86 49.53,22.86 50.8,21.59 50.8,16.51 49.53,15.24 JP4.3 R10.2
PORTB4
  Top 0.61: JP2.1 29.21,34.29 33.02,38.1 41.91,38.1 43.18,36.83 IC1.18 43.18,33.02 52.07,24.13 52.07,6.35 50.8,5.08 27.94,5.08 26.67,6.35 26.67,15.24 24.13,17.78 JP3.2
PORTB5
  Top 0.61: IC1.19 45.72,38.1 44.45,39.37 30.48,39.37 27.94,36.83 JP2.3
  Bottom 0.61: JP4.5 49.53,10.16 50.8,11.43 50.8,27.94 45.72,33.02 IC1.19
PORTB_A0
  Top 0.61: IC2.1 JP5.2 JP5.1 R6.2
PORTB_A1
  Top 0.61: R5.2 JP5.3 JP5.4 IC2.2
PORTB_A2
  Top 0.61: R4.2 JP5.5 JP5.6 IC2.3
PORTB_A3
  Top 0.61: R3.2 JP5.7 JP5.8 IC2.4
PORTB_A4
  Top 0.61: IC2.5 JP5.10 JP5.9
PORTB_A5
  Top 0.406: JP1.4 31.75,83.82 41.91,83.82 43.18,85.09 JP5.11
  Top 0.61: IC2.6 JP5.12 JP5.11
PORTB_A6
  Top 0.61: IC2.7 JP5.14 JP5.13
  Bottom 0.61: JP1.1 40.64,80.01 43.18,82.55 JP5.13
PORTB_A7
  Top 0.61: IC2.8 JP5.16 JP5.15 44.45,80.01 41.91,82.55 JP1.3
PORTC0
  Top 0.406: JP6.1 45.72,62.23 46.99,63.5 54.61,63.5 55.88,64.77 IC2.14
PORTC1
  Top 0.406: JP6.2 53.34,60.96 54.61,62.23 IC2.15
PORTC2
  Top 0.406: IC2.16 46.99,59.69 JP6.3
PORTC3
  Top 0.406: IC2.17 54.61,57.15 53.34,58.42 JP6.4
PORTC4
  Top 0.406: JP6.5 46.99,57.15 52.07,57.15 54.61,54.61 IC2.18
PORTC5
  Top 0.406: JP6.6 50.8,55.88 54.61,52.07 IC2.19
PORTC6
  Top 0.406: IC2.20 52.07,49.53 49.53,52.07 46.99,52.07 JP6.7
PORTC7
  Top 0.406: JP6.8 50.8,53.34 53.34,50.8 68.58,50.8 69.85,49.53 IC2.21
VCC
  Bottom 1.27: IC8.2 31.75,53.34 C8.+ 41.91,52.07 43.18,50.8 JP6.9

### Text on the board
Bottom: CONTROL DE PARQUEADEROS | UNIANDES 2010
